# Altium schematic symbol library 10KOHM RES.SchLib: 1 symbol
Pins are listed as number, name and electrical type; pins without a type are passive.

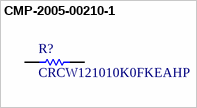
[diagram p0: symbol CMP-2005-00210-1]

## CMP-2005-00210-1
designator R?, comment CRCW121010K0FKEAHP
Manufacturer: Vishay Dale
footprint RESC3225X60X45ML20T20 (Chip Resistor, 2-Leads, Body 3.20x2.50mm, IPC Low Density)
footprint RESC3225X60X45NL20T20 (Chip Resistor, 2-Leads, Body 3.20x2.50mm, IPC Medium Density)
footprint RESC3225X60X45LL20T20 (Chip Resistor, 2-Leads, Body 3.20x2.50mm, IPC High Density)
pins: 1, 2
1 alternate drawing of the same symbol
